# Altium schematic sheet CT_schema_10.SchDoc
size 278 x 170 mm
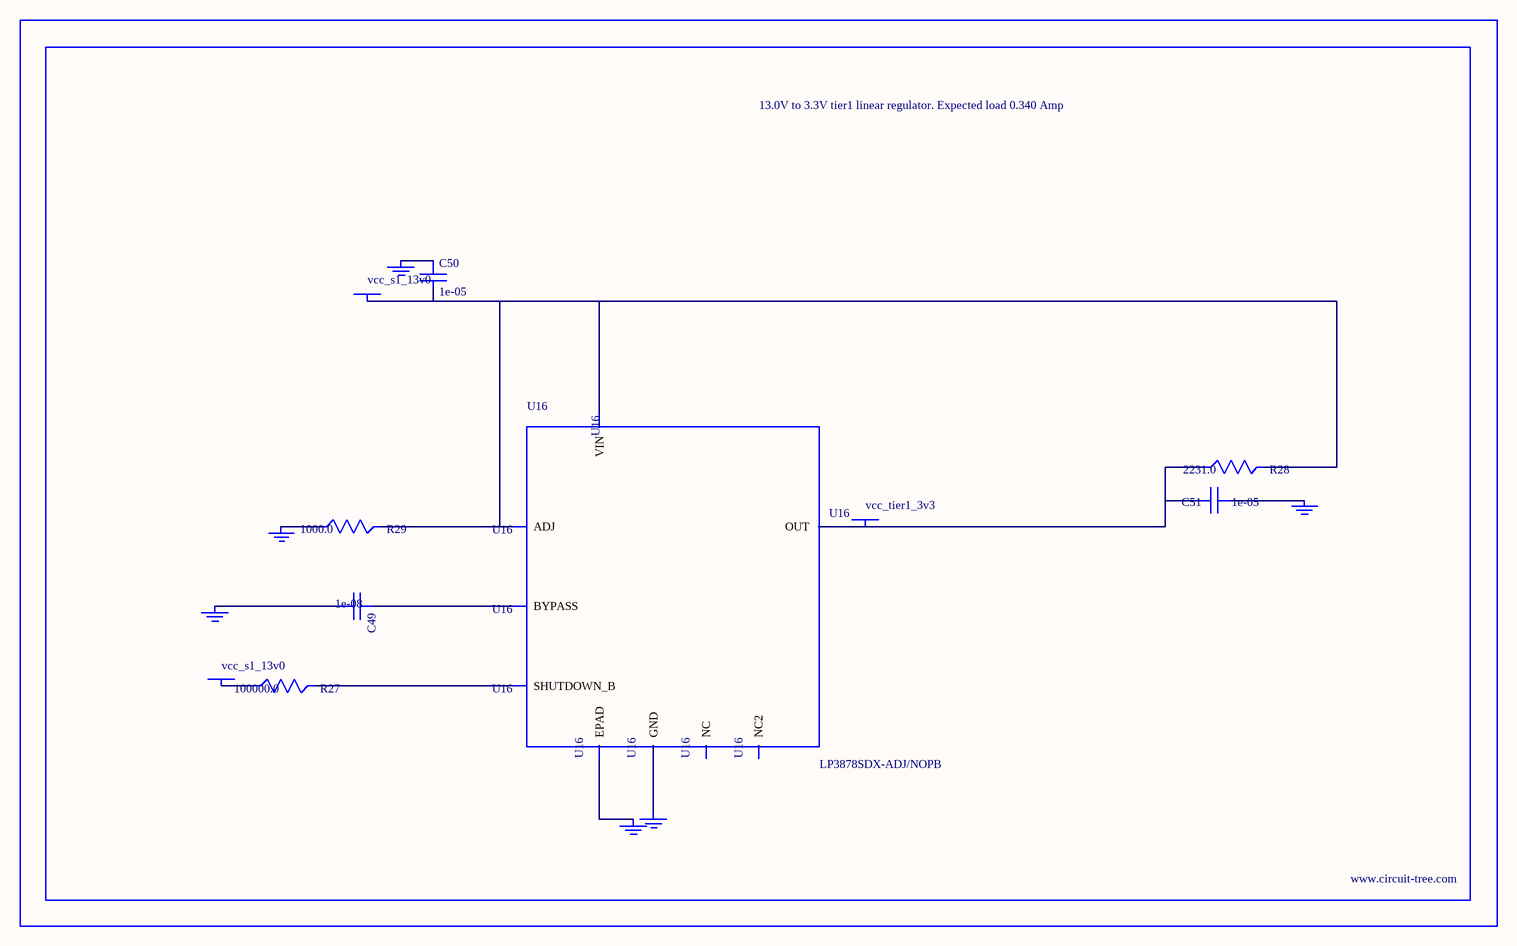
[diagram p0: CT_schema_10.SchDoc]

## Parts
BORDER9  (no value)
C49  1e-08  [C0402]
C50  1e-05  [C1210]
C51  1e-05  [C1210]
GND_INSTANCE_9_0  (no value)
GND_INSTANCE_9_1  (no value)
GND_INSTANCE_9_2  (no value)
GND_INSTANCE_9_3  (no value)
GND_INSTANCE_9_4  (no value)
GND_INSTANCE_9_5  (no value)
POWER_INSTANCE_9_0  vcc_s1_13v0
POWER_INSTANCE_9_1  vcc_s1_13v0
POWER_INSTANCE_9_2  vcc_tier1_3v3
R27  100000.0  [R0603]
R28  2231.0  [R0603]
R29  1000.0  [R0603]
U16  LP3878SDX-ADJ/NOPB  [WSON-8]

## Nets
NetC49_1: C49.1 U16.1(BYPASS)
NetC49_2: C49.2 GND_INSTANCE_9_0.0(GND)
NetC50_1: C50.1 GND_INSTANCE_9_1.0(GND)
NetC50_2: C50.2 POWER_INSTANCE_9_0.0(PWR) R28.2 R29.2 U16.4(VIN) U16.6(ADJ)
NetC51_1: C51.1 GND_INSTANCE_9_2.0(GND)
NetC51_2: C51.2 POWER_INSTANCE_9_2.0(PWR) R28.1 U16.5(OUT)
NetGND_INSTANCE_9_3_0: GND_INSTANCE_9_3.0(GND) R29.1
NetGND_INSTANCE_9_4_0: GND_INSTANCE_9_4.0(GND) U16.PAD(EPAD)
NetGND_INSTANCE_9_5_0: GND_INSTANCE_9_5.0(GND) U16.3(GND)
NetPOWER_INSTANCE_9_1_0: POWER_INSTANCE_9_1.0(PWR) R27.1
NetR27_2: R27.2 U16.8(SHUTDOWN_B)

Not connected (* = marked no-connect by the designer): U16 2(NC) 7(NC2)

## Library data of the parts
BORDER9 = BORDER_PAGE9
C49 = C0402C103K3RAC
C50 = C1210C106K5PACTU
C51 = GRM32DR61E106MA12L
GND_INSTANCE_9_0-GND_INSTANCE_9_5 = GND
POWER_INSTANCE_9_0-POWER_INSTANCE_9_2 = PWR
R27 = RC0603JR-07100KL
R28 = R28
R29 = RC0603JR-071KL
